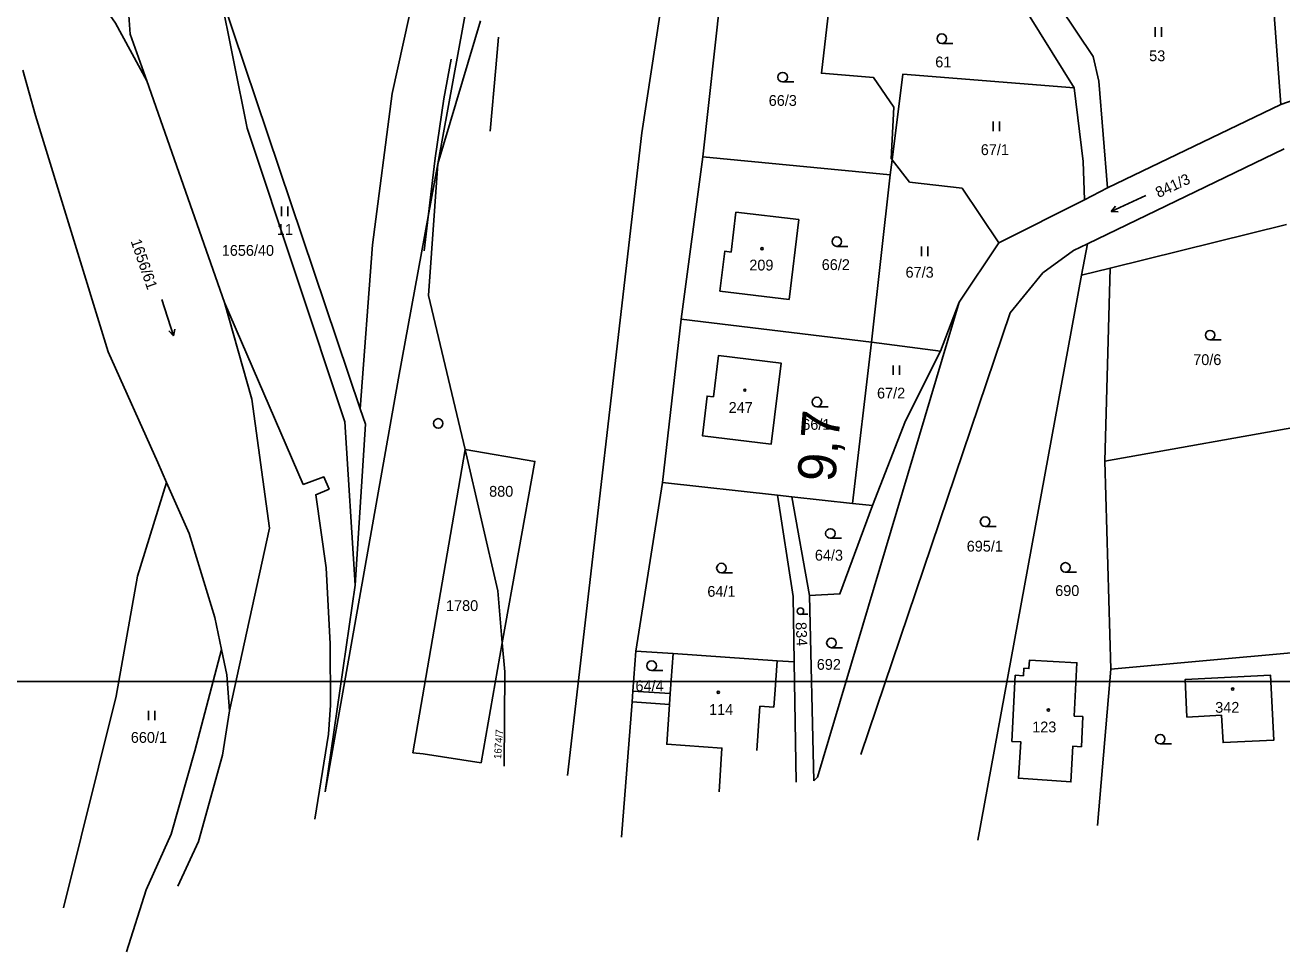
# Model space of a CAD drawing. Extents: x -553916 to -552953, y -1067470 to -1066637.
# Drawn here: x -553675.3 to -553477.6, y -1067452.8 to -1067307 of the extents above; entities that cross this region are included whole.
import ezdxf

# ---------------------------------------------------------------- set-up
doc = ezdxf.new("R2010")
doc.units = 0
for name, color, linetype in [('El2015-Kolej', 7, 'Continuous'), ('Hranice parcel', 7, 'Continuous'), ('Návěst místo trati', 7, 'Continuous'), ('Parcelní čísla', 7, 'Continuous'), ('Vnitřní kresba', 7, 'Continuous'), ('Vrstva 1', 7, 'Continuous'), ('Značky budov', 7, 'Continuous'), ('Značky kultur', 7, 'Continuous')]:
    doc.layers.add(name, color=color, linetype=linetype)

msp = doc.modelspace()

# ---------------------------------------------------------------- linework, layer by layer
at = {"layer": 'El2015-Kolej'}
for points in [[(-553602.15, -1067323.68), (-553601.29, -1067313.74), (-553600.88, -1067308.88)], [(-553612.55, -1067342.51), (-553611.94, -1067337.18), (-553610.81, -1067327.96), (-553609.44, -1067318.59), (-553608.32, -1067312.37)]]:
    msp.add_lwpolyline(points, dxfattribs=at)
at = {"layer": 'Hranice parcel'}
for p, q in [((-553658.81, -1067308.41), (-553660.7, -1067281.64)), ((-553564.68, -1067291.26), (-553568.7, -1067327.71)), ((-553477.8, -1067319.49), (-553479.96, -1067289.49)), ((-553510.29, -1067316.85), (-553521.28, -1067299.18)), ((-553644.72, -1067301.75), (-553622.6, -1067367.36)), ((-553603.7, -1067306.34), (-553610.41, -1067328.83)), ((-553656.17, -1067315.75), (-553658.81, -1067308.41)), ((-553477.8, -1067319.49), (-553452.48, -1067310.66)), ((-553656.17, -1067315.75), (-553643.98, -1067350.66)), ((-553505.07, -1067332.62), (-553477.8, -1067319.49)), ((-553477.28, -1067326.46), (-553508.22, -1067341.4)), ((-553610.41, -1067328.83), (-553611.87, -1067349.52)), ((-553568.7, -1067327.71), (-553572.11, -1067353.26)), ((-553539.25, -1067330.57), (-553568.7, -1067327.71)), ((-553539.25, -1067330.57), (-553538.95, -1067328.2)), ((-553539.08, -1067328.03), (-553538.95, -1067328.2)), ((-553538.95, -1067328.2), (-553536.18, -1067331.71)), ((-553536.18, -1067331.71), (-553527.91, -1067332.68)), ((-553527.91, -1067332.68), (-553522.13, -1067341.26)), ((-553508.66, -1067334.49), (-553505.07, -1067332.62)), ((-553522.13, -1067341.26), (-553508.66, -1067334.49)), ((-553504.63, -1067345.23), (-553476.87, -1067338.35)), ((-553528.38, -1067350.6), (-553522.13, -1067341.26)), ((-553508.22, -1067341.4), (-553509.15, -1067346.35)), ((-553509.15, -1067346.35), (-553525.44, -1067435.26)), ((-553509.15, -1067346.35), (-553504.63, -1067345.23)), ((-553505.45, -1067375.59), (-553504.63, -1067345.23)), ((-553643.98, -1067350.66), (-553631.57, -1067379.26)), ((-553611.87, -1067349.52), (-553606.12, -1067373.77)), ((-553528.38, -1067350.6), (-553531.3, -1067358.3)), ((-553572.11, -1067353.26), (-553575.04, -1067378.95)), ((-553542.19, -1067356.9), (-553572.11, -1067353.26)), ((-553545.17, -1067382.25), (-553542.19, -1067356.9)), ((-553531.3, -1067358.3), (-553542.19, -1067356.9)), ((-553469.3, -1067369.18), (-553505.45, -1067375.59)), ((-553606.12, -1067373.77), (-553600.95, -1067396.02)), ((-553653.09, -1067378.96), (-553654.47, -1067375.83)), ((-553505.45, -1067375.59), (-553504.51, -1067408.36)), ((-553649.54, -1067386.98), (-553653.09, -1067378.96)), ((-553575.04, -1067378.95), (-553579.28, -1067405.5)), ((-553556.95, -1067380.95), (-553575.04, -1067378.95)), ((-553556.95, -1067380.95), (-553554.72, -1067381.2)), ((-553545.17, -1067382.25), (-553554.72, -1067381.2)), ((-553554.72, -1067381.2), (-553551.91, -1067396.75)), ((-553542.03, -1067382.59), (-553545.17, -1067382.25)), ((-553645.48, -1067400.22), (-553649.54, -1067386.98)), ((-553628.1, -1067427.64), (-553623.42, -1067395.12)), ((-553600.95, -1067396.02), (-553600.26, -1067404.19)), ((-553600.95, -1067396.02), (-553600.26, -1067404.19)), ((-553551.91, -1067396.75), (-553551.23, -1067425.89)), ((-553644.44, -1067405.24), (-553645.48, -1067400.22)), ((-553600.26, -1067404.19), (-553603.6, -1067423.08)), ((-553579.71, -1067411.78), (-553579.28, -1067405.5)), ((-553579.28, -1067405.5), (-553573.4, -1067405.9)), ((-553504.51, -1067408.36), (-553475.58, -1067405.74)), ((-553554.04, -1067426.13), (-553554.35, -1067407.2)), ((-553506.64, -1067432.96), (-553504.51, -1067408.36)), ((-553579.71, -1067411.78), (-553579.83, -1067413.47)), ((-553579.83, -1067413.47), (-553581.5, -1067434.75)), ((-553627.58, -1067418.54), (-553629.74, -1067431.93))]:
    msp.add_line(p, q, dxfattribs=at)
for points in [[(-553590.02, -1067425.05), (-553578.3, -1067323.96), (-553571.08, -1067276.6), (-553571.65, -1067255.09), (-553574.19, -1067242.71)], [(-553679.12, -1067280.91), (-553661.1, -1067306.72), (-553656.17, -1067315.75)], [(-553520.36, -1067292.41), (-553507.33, -1067311.94), (-553506.4, -1067315.83), (-553505.07, -1067332.62)], [(-553644.72, -1067301.75), (-553640.4, -1067323.22), (-553625.01, -1067369.42), (-553623.42, -1067395.12)], [(-553548.89, -1067304.57), (-553550.06, -1067314.58), (-553541.86, -1067315.26), (-553538.68, -1067319.9), (-553539.08, -1067328.03)], [(-553654.47, -1067375.83), (-553662.26, -1067358.39), (-553673.71, -1067321.24), (-553675.68, -1067314.09)], [(-553538.95, -1067328.2), (-553537.23, -1067314.72), (-553510.29, -1067316.85)], [(-553510.29, -1067316.85), (-553508.9, -1067328.46), (-553508.66, -1067334.49)], [(-553542.19, -1067356.9), (-553542.12, -1067356.43), (-553539.25, -1067330.57)], [(-553563.51, -1067336.41), (-553553.63, -1067337.6), (-553555.15, -1067350.16), (-553566.02, -1067348.84), (-553565.27, -1067342.59), (-553564.27, -1067342.71), (-553563.51, -1067336.41)], [(-553508.22, -1067341.4), (-553510.38, -1067342.44), (-553515.22, -1067345.99), (-553520.38, -1067352.25), (-553543.87, -1067421.79)], [(-553643.17, -1067414.9), (-553636.88, -1067386.17), (-553639.67, -1067365.88), (-553643.98, -1067350.66)], [(-553551.23, -1067425.89), (-553550.67, -1067425.31), (-553528.38, -1067350.6)], [(-553531.3, -1067358.3), (-553536.84, -1067369.26), (-553542.03, -1067382.59)], [(-553567.04, -1067365.48), (-553566.24, -1067358.98), (-553556.41, -1067360.17), (-553557.95, -1067372.93), (-553568.79, -1067371.62), (-553568.04, -1067365.36), (-553567.04, -1067365.48)], [(-553623.42, -1067395.12), (-553621.8, -1067369.77), (-553622.6, -1067367.36)], [(-553606.12, -1067373.77), (-553595.12, -1067375.65), (-553600.26, -1067404.19)], [(-553631.57, -1067379.26), (-553628.31, -1067378.1), (-553627.5, -1067380.01), (-553629.62, -1067380.89), (-553627.95, -1067392.42), (-553627.34, -1067404.34), (-553627.3, -1067414.01), (-553627.58, -1067418.54)], [(-553669.27, -1067445.9), (-553661.03, -1067412.6), (-553657.63, -1067393.68), (-553653.09, -1067378.96)], [(-553554.35, -1067407.2), (-553554.52, -1067396.92), (-553556.95, -1067380.95)], [(-553551.91, -1067396.75), (-553547.15, -1067396.49), (-553542.03, -1067382.59)], [(-553659.4, -1067452.82), (-553656.26, -1067443.05), (-553652.34, -1067434.28), (-553648.64, -1067421.21), (-553644.44, -1067405.24)], [(-553643.17, -1067414.9), (-553643.61, -1067409.25), (-553644.44, -1067405.24)], [(-553600.26, -1067404.19), (-553599.87, -1067408.74), (-553599.97, -1067423.61)], [(-553600.26, -1067404.19), (-553599.87, -1067408.74), (-553599.97, -1067423.61)], [(-553573.4, -1067405.9), (-553573.83, -1067412.18), (-553579.71, -1067411.78)], [(-553554.35, -1067407.2), (-553557.04, -1067407.02), (-553573.4, -1067405.9)], [(-553520.12, -1067419.71), (-553518.67, -1067419.79), (-553519.07, -1067425.49), (-553510.8, -1067426.07), (-553510.52, -1067420.48), (-553509.17, -1067420.55), (-553508.94, -1067415.79), (-553510.29, -1067415.72), (-553509.86, -1067407.33), (-553517.34, -1067406.94), (-553517.41, -1067408.24), (-553518.21, -1067408.2), (-553518.27, -1067409.37), (-553519.57, -1067409.3), (-553520.12, -1067419.71)], [(-553487.11, -1067415.6), (-553492.55, -1067415.89), (-553492.85, -1067409.99), (-553479.42, -1067409.27), (-553478.87, -1067419.49), (-553486.87, -1067419.9), (-553487.11, -1067415.6)], [(-553579.83, -1067413.47), (-553573.95, -1067413.88), (-553574.38, -1067420.16), (-553565.7, -1067420.76), (-553566.17, -1067427.63)], [(-553651.28, -1067442.47), (-553648.07, -1067435.48), (-553644.26, -1067421.89), (-553643.17, -1067414.9)]]:
    msp.add_lwpolyline(points, dxfattribs=at)
at = {"layer": 'Návěst místo trati'}
msp.add_circle((-553610.34, -1067369.67), 0.75, dxfattribs=at)
at = {"layer": 'Vnitřní kresba'}
for p, q in [((-553557.04, -1067407.02), (-553557.36, -1067411.61)), ((-553557.54, -1067414.3), (-553557.36, -1067411.61)), ((-553573.83, -1067412.18), (-553573.95, -1067413.88)), ((-553560.22, -1067421.14), (-553559.74, -1067414.15)), ((-553559.74, -1067414.15), (-553557.54, -1067414.3))]:
    msp.add_line(p, q, dxfattribs=at)
at = {"layer": 'Vrstva 1'}
for p, q in [((-553610.41, -1067328.83), (-553603.7, -1067306.34)), ((-553610.41, -1067328.83), (-553611.87, -1067349.52)), ((-553622.6, -1067367.36), (-553620.69, -1067341.58)), ((-553611.87, -1067349.52), (-553606.12, -1067373.77)), ((-553606.12, -1067373.77), (-553600.95, -1067396.02)), ((-552953.11, -1067410.27), (-553794.11, -1067410.27))]:
    msp.add_line(p, q, dxfattribs=at)
for points in [[(-553576.73, -1067221.16), (-553579.9, -1067226.28), (-553584.2, -1067237.72), (-553592.61, -1067257.79), (-553598.74, -1067274.59), (-553603.72, -1067298.29), (-553604.8, -1067298.11), (-553610.41, -1067328.83)], [(-553620.69, -1067341.58), (-553617.56, -1067317.76), (-553612.15, -1067293.03), (-553604.5, -1067271.72), (-553593.43, -1067246.52), (-553584.77, -1067229.49)], [(-553610.41, -1067328.83), (-553616.57, -1067362.55), (-553628.1, -1067427.64)], [(-553603.6, -1067423.08), (-553612.7, -1067421.66), (-553614.31, -1067421.48), (-553606.12, -1067373.77)]]:
    msp.add_lwpolyline(points, dxfattribs=at)
at = {"layer": 'Značky budov'}
for centre in [(-553559.39, -1067342.19), (-553562.1, -1067364.44), (-553566.29, -1067411.99), (-553485.36, -1067411.47), (-553514.35, -1067414.77)]:
    msp.add_circle(centre, 0.175, dxfattribs=at)
at = {"layer": 'Značky kultur'}
for p, q in [((-553497.58, -1067308.83), (-553497.58, -1067307.33)), ((-553496.58, -1067308.83), (-553496.58, -1067307.33)), ((-553531.12, -1067309.88), (-553529.37, -1067309.88)), ((-553556.16, -1067315.94), (-553554.41, -1067315.94)), ((-553523.06, -1067323.69), (-553523.06, -1067322.19)), ((-553522.06, -1067323.69), (-553522.06, -1067322.19)), ((-553499.02, -1067333.81), (-553504.46, -1067336.35)), ((-553635, -1067337.06), (-553635, -1067335.56)), ((-553634, -1067337.06), (-553634, -1067335.56)), ((-553504.46, -1067336.35), (-553503.78, -1067335.48)), ((-553504.46, -1067336.35), (-553503.36, -1067336.39)), ((-553547.64, -1067341.81), (-553545.89, -1067341.81)), ((-553534.33, -1067343.34), (-553534.33, -1067341.84)), ((-553533.33, -1067343.34), (-553533.33, -1067341.84)), ((-553653.82, -1067350.2), (-553651.97, -1067355.9)), ((-553651.97, -1067355.9), (-553652.74, -1067355.13)), ((-553651.97, -1067355.9), (-553651.79, -1067354.82)), ((-553488.91, -1067356.53), (-553487.16, -1067356.53)), ((-553538.77, -1067362.05), (-553538.77, -1067360.55)), ((-553537.77, -1067362.05), (-553537.77, -1067360.55)), ((-553550.77, -1067367.06), (-553549.02, -1067367.06)), ((-553524.31, -1067385.88), (-553522.56, -1067385.88)), ((-553548.65, -1067387.74), (-553546.9, -1067387.74)), ((-553565.79, -1067393.18), (-553564.04, -1067393.18)), ((-553511.67, -1067393.08), (-553509.92, -1067393.08)), ((-553553.35, -1067399.71), (-553552.18, -1067399.71)), ((-553548.49, -1067404.96), (-553546.74, -1067404.96)), ((-553576.77, -1067408.54), (-553575.02, -1067408.54)), ((-553655.91, -1067416.38), (-553655.91, -1067414.88)), ((-553654.91, -1067416.38), (-553654.91, -1067414.88)), ((-553496.76, -1067420.11), (-553495.01, -1067420.11))]:
    msp.add_line(p, q, dxfattribs=at)
for centre, radius in [((-553531.12, -1067309.13), 0.75), ((-553556.16, -1067315.19), 0.75), ((-553547.64, -1067341.06), 0.75), ((-553488.91, -1067355.78), 0.75), ((-553550.77, -1067366.31), 0.75), ((-553548.65, -1067386.99), 0.75), ((-553524.31, -1067385.13), 0.75), ((-553565.79, -1067392.43), 0.75), ((-553511.67, -1067392.33), 0.75), ((-553553.36, -1067399.21), 0.502), ((-553548.49, -1067404.21), 0.75), ((-553576.77, -1067407.79), 0.75), ((-553496.76, -1067419.36), 0.75)]:
    msp.add_circle(centre, radius, dxfattribs=at)

# ---------------------------------------------------------------- texts
at = {"layer": 'Návěst místo trati'}
msp.add_text('9,7', height=6, rotation=85.4407, dxfattribs=at).set_placement((-553547.89, -1067379.01))
at = {"layer": 'Parcelní čísla'}
for s, p in [('53', (-553498.5, -1067312.68)), ('61', (-553532.15, -1067313.65)), ('66/3', (-553558.35, -1067319.71)), ('67/1', (-553524.99, -1067327.45)), ('11', (-553635.73, -1067340.01)), ('1656/40', (-553644.39, -1067343.3)), ('209', (-553561.4, -1067345.61)), ('66/2', (-553550.01, -1067345.54)), ('67/3', (-553536.82, -1067346.74)), ('70/6', (-553491.57, -1067360.49)), ('67/2', (-553541.31, -1067365.75)), ('247', (-553564.65, -1067368.01)), ('66/1', (-553553.07, -1067370.68)), ('880', (-553602.33, -1067381.21)), ('695/1', (-553527.2, -1067389.84)), ('64/3', (-553551.09, -1067391.26)), ('64/1', (-553568, -1067396.95)), ('690', (-553513.28, -1067396.83)), ('692', (-553550.79, -1067408.44)), ('64/4', (-553579.31, -1067411.82)), ('114', (-553567.73, -1067415.54)), ('342', (-553488.11, -1067415.2)), ('123', (-553516.9, -1067418.28)), ('660/1', (-553658.7, -1067419.93))]:
    msp.add_text(s, height=1.7, dxfattribs=at).set_placement(p)
for s, height, rotation, p in [('841/3', 1.7, 25, (-553497.02, -1067334.22)), ('1656/61', 1.7, 289, (-553658.75, -1067340.99)), ('834', 1.7, 273, (-553554.13, -1067400.97)), ('1674/7', 1.14, 86, (-553600.46, -1067422.51))]:
    msp.add_text(s, height=height, rotation=rotation, dxfattribs=at).set_placement(p)
at = {"layer": 'Vrstva 1'}
msp.add_text('1780', height=1.7, dxfattribs=at).set_placement((-553609.11, -1067399.19))

doc.saveas('drawing.dxf')
